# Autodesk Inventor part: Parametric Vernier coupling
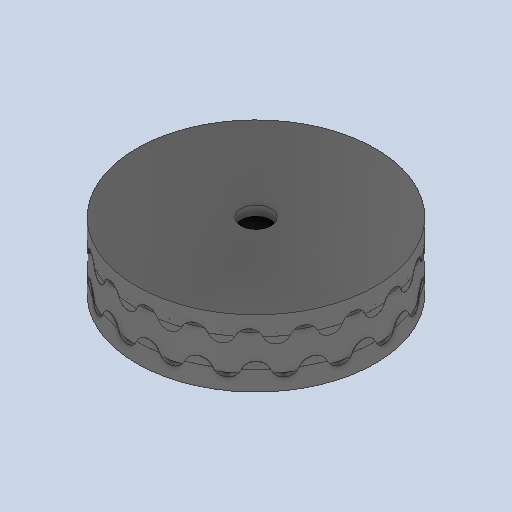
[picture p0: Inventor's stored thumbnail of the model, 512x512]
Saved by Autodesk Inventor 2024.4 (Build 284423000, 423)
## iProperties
Created: 2025-12
Part Number: Parametric Vernier coupling
Material: Generic
Document SubType Name: Modeling
Designer: AdminForWorker
Density: 1 g/cm^3
Appearance: Default
Title: Parametric Vernier coupling v2
Author: AdminForWorker
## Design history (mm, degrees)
feature "Body1"
feature "Body2"
feature "Body3"
body "Solid1"
body "Solid2"
body "Solid3"
